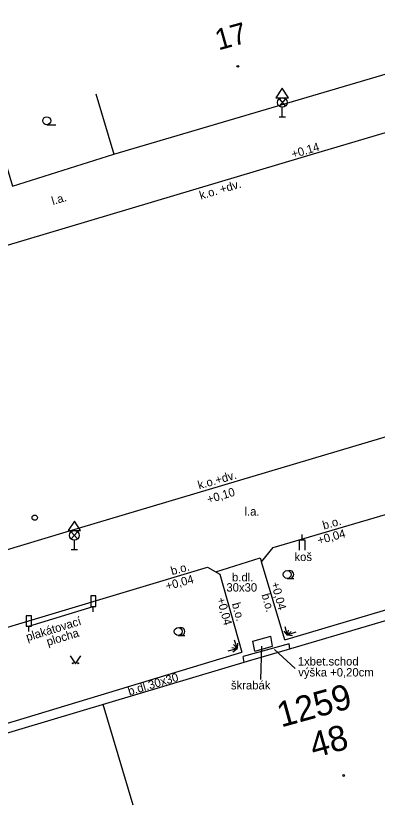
# Model space of a CAD drawing. Extents: x -597333 to -596488, y -1158921 to -1158644.
# Drawn here: x -596773.1 to -596755.95, y -1158752.5 to -1158714.98 of the extents above; entities that cross this region are included whole.
import ezdxf

# ---------------------------------------------------------------- set-up
doc = ezdxf.new("R2010")
doc.units = 0
for name, color, linetype in [('Vrstva 10', 7, 'Continuous'), ('Vrstva 14', 7, 'Continuous'), ('Vrstva 15', 7, 'Continuous'), ('Vrstva 24', 7, 'Continuous'), ('Vrstva 4', 7, 'Continuous'), ('Vrstva 43', 7, 'Continuous'), ('Vrstva 44', 7, 'Continuous'), ('Vrstva 49', 7, 'Continuous'), ('Vrstva 5', 7, 'Continuous'), ('Vrstva 50', 7, 'Continuous'), ('Vrstva 7', 7, 'Continuous')]:
    doc.layers.add(name, color=color, linetype=linetype)

msp = doc.modelspace()

# ---------------------------------------------------------------- linework, layer by layer
at = {"layer": 'Vrstva 10'}
msp.add_lwpolyline([(-596775.29, -1158716.24), (-596773.25, -1158723.07), (-596768.45, -1158721.56)], dxfattribs=at)
at = {"layer": 'Vrstva 14'}
for p, q in [((-596771.63, -1158720.156), (-596771.192, -1158720.156)), ((-596760.22, -1158741.718), (-596759.907, -1158741.718)), ((-596765.39, -1158744.428), (-596765.078, -1158744.428))]:
    msp.add_line(p, q, dxfattribs=at)
msp.add_lwpolyline([(-596770.515, -1158745.398), (-596770.265, -1158745.773), (-596770.015, -1158745.398)], dxfattribs=at)
for centre, radius in [((-596771.63, -1158719.968), 0.188), ((-596760.22, -1158741.53), 0.188), ((-596765.39, -1158744.24), 0.188), ((-596770.39, -1158745.748), 0.025), ((-596770.14, -1158745.748), 0.025)]:
    msp.add_circle(centre, radius, dxfattribs=at)
for centre in [(-596760.095, -1158741.53), (-596765.265, -1158744.24)]:
    msp.add_arc(centre, 0.188, 249.4944, 109.0474, dxfattribs=at)
at = {"layer": 'Vrstva 15'}
for p, q in [((-596759.51, -1158739.88), (-596759.51, -1158739.63)), ((-596772.48, -1158743.99), (-596769.42, -1158743.05)), ((-596769.42, -1158743.3), (-596769.42, -1158743.05)), ((-596772.48, -1158744.24), (-596772.48, -1158743.99))]:
    msp.add_line(p, q, dxfattribs=at)
msp.add_lwpolyline([(-596759.635, -1158740.38), (-596759.635, -1158739.88), (-596759.385, -1158739.88), (-596759.385, -1158740.38)], dxfattribs=at)
for points in [[(-596769.545, -1158743.05), (-596769.295, -1158743.05), (-596769.295, -1158742.55), (-596769.545, -1158742.55)], [(-596772.605, -1158743.99), (-596772.355, -1158743.99), (-596772.355, -1158743.49), (-596772.605, -1158743.49)]]:
    msp.add_lwpolyline(points, close=True, dxfattribs=at)
for centre in [(-596762.562, -1158717.382), (-596757.537, -1158751.081)]:
    msp.add_circle(centre, 0.0438, dxfattribs=at)
at = {"layer": 'Vrstva 24'}
msp.add_circle((-596772.2, -1158738.83), 0.125, dxfattribs=at)
at = {"layer": 'Vrstva 4'}
for p, q in [((-596769.301, -1158718.683), (-596768.45, -1158721.56)), ((-596760.468, -1158745.173), (-596744.352, -1158740.392)), ((-596767.525, -1158752.495), (-596768.956, -1158747.704))]:
    msp.add_line(p, q, dxfattribs=at)
for points in [[(-596768.45, -1158721.56), (-596752.997, -1158716.989)], [(-596760.09, -1158745.061), (-596760.13, -1158744.82), (-596762.31, -1158745.43)], [(-596762.264, -1158745.707), (-596762.31, -1158745.43)], [(-596778.32, -1158750.5), (-596761.94, -1158745.61)]]:
    msp.add_lwpolyline(points, dxfattribs=at)
at = {"layer": 'Vrstva 44'}
for p, q in [((-596760.3, -1158718.93), (-596760.6, -1158719.274)), ((-596760.6, -1158718.93), (-596760.3, -1158719.274)), ((-596760.45, -1158719.78), (-596760.45, -1158719.33)), ((-596760.6, -1158719.78), (-596760.3, -1158719.78)), ((-596770.17, -1158739.5), (-596770.47, -1158739.844)), ((-596770.47, -1158739.5), (-596770.17, -1158739.844)), ((-596770.32, -1158740.35), (-596770.32, -1158739.9)), ((-596770.47, -1158740.35), (-596770.17, -1158740.35))]:
    msp.add_line(p, q, dxfattribs=at)
for points in [[(-596760.75, -1158718.874), (-596760.15, -1158718.874), (-596760.45, -1158718.424), (-596760.75, -1158718.874)], [(-596770.62, -1158739.444), (-596770.02, -1158739.444), (-596770.32, -1158738.994), (-596770.62, -1158739.444)]]:
    msp.add_lwpolyline(points, dxfattribs=at)
for centre in [(-596760.45, -1158719.102), (-596770.32, -1158739.672)]:
    msp.add_circle(centre, 0.228, dxfattribs=at)
at = {"layer": 'Vrstva 49'}
for p, q in [((-596760.373, -1158744.226), (-596760.215, -1158744.419)), ((-596760.169, -1158744.174), (-596760.215, -1158744.419)), ((-596760.036, -1158744.245), (-596760.215, -1158744.419)), ((-596759.966, -1158744.445), (-596760.215, -1158744.419)), ((-596762.844, -1158744.999), (-596762.599, -1158745.045)), ((-596762.792, -1158745.203), (-596762.599, -1158745.045)), ((-596762.773, -1158744.865), (-596762.599, -1158745.045)), ((-596762.573, -1158744.796), (-596762.599, -1158745.045))]:
    msp.add_line(p, q, dxfattribs=at)
for points in [[(-596760.322, -1158743.999), (-596760.215, -1158744.419)], [(-596759.805, -1158744.277), (-596760.215, -1158744.419)], [(-596762.741, -1158744.635), (-596762.599, -1158745.045)], [(-596763.019, -1158745.152), (-596762.599, -1158745.045)], [(-596761.438, -1158744.943), (-596761.488, -1158746.527)], [(-596760.816, -1158745.102), (-596759.838, -1158745.993)]]:
    msp.add_lwpolyline(points, dxfattribs=at)
at = {"layer": 'Vrstva 5'}
msp.add_line((-596761.94, -1158745.61), (-596760.469, -1158745.171), dxfattribs=at)
at = {"layer": 'Vrstva 7'}
msp.add_line((-596760.33, -1158744.63), (-596744.76, -1158740.02), dxfattribs=at)
for points in [[(-596838.86, -1158745.39), (-596830.57, -1158742.87), (-596825.17, -1158741.29), (-596822.55, -1158740.48), (-596812.47, -1158737.51), (-596803.27, -1158734.78), (-596791.33, -1158731.21), (-596774.68, -1158726.23), (-596759.56, -1158721.71), (-596748.14, -1158718.32), (-596736.94, -1158714.98)], [(-596782.84, -1158743.16), (-596770.71, -1158739.5), (-596748.23, -1158732.81), (-596734.11, -1158728.61), (-596733.99, -1158728.79), (-596728.47, -1158727.15), (-596728.46, -1158726.93), (-596719.98, -1158724.4)], [(-596760.89, -1158740.25), (-596746.61, -1158736.05), (-596745.96, -1158736.23), (-596745.66, -1158737.13), (-596744.76, -1158740.02)], [(-596760.33, -1158744.63), (-596761.43, -1158740.93), (-596760.89, -1158740.25)], [(-596763.6, -1158741.41), (-596761.5, -1158740.74), (-596761.43, -1158740.93)], [(-596778.92, -1158745.66), (-596764, -1158741.19), (-596763.41, -1158741.51), (-596762.37, -1158745.23)], [(-596761.85, -1158744.7), (-596761, -1158744.46)], [(-596761.76, -1158745.17), (-596761.85, -1158744.7)], [(-596761.76, -1158745.17), (-596760.91, -1158744.93), (-596761, -1158744.46)], [(-596773.07, -1158748.47), (-596762.37, -1158745.23)], [(-596778.92, -1158745.66), (-596779.34, -1158746.2), (-596778.16, -1158749.96), (-596773.07, -1158748.47)]]:
    msp.add_lwpolyline(points, dxfattribs=at)

# ---------------------------------------------------------------- texts
at = {"layer": 'Vrstva 43'}
for s, height, p in [('17', 1, (-596763.479, -1158716.629)), ('1259', 1.2, (-596760.505, -1158748.806)), ('48', 1.2, (-596758.951, -1158750.261))]:
    msp.add_text(s, height=height, rotation=15.5254, dxfattribs=at).set_placement(p)
at = {"layer": 'Vrstva 49'}
for s, rotation, p in [('k.o. +dv.', 16.569, (-596764.317, -1158723.717)), ('l.a.', 16.5505, (-596771.335, -1158723.977)), ('k.o.+dv.', 16.0773, (-596764.397, -1158737.488)), ('b.o.', 15.3727, (-596758.479, -1158739.395)), ('b.o.', 15.3727, (-596765.682, -1158741.567)), ('b.o.', 285.3727, (-596761.437, -1158742.491)), ('b.o.', 285.3727, (-596762.849, -1158742.922)), ('plakátovací', 17.0764, (-596772.544, -1158744.708)), ('plocha', 17.0764, (-596771.572, -1158744.932)), ('b.dl.30x30', 16.6222, (-596767.71, -1158747.283))]:
    msp.add_text(s, height=0.4, rotation=rotation, dxfattribs=at).set_placement(p)
for s, p in [('l.a.', (-596762.245, -1158738.732)), ('koš', (-596759.873, -1158740.892)), ('b.dl.', (-596762.836, -1158741.858)), ('30x30', (-596763.103, -1158742.344)), ('1xbet.schod', (-596759.713, -1158745.857)), ('škrabák', (-596762.888, -1158746.993))]:
    msp.add_text(s, height=0.4, dxfattribs=at).set_placement(p)
at = {"layer": 'Vrstva 50'}
for s, rotation, p in [('+0.14', 16.5375, (-596759.952, -1158721.758)), ('+0,10', 16.8584, (-596763.956, -1158738.167)), ('+0,04', 15.3727, (-596758.722, -1158740.11)), ('+0,04', 15.3727, (-596765.925, -1158742.282)), ('+0,04', 285.3727, (-596760.99, -1158741.944)), ('+0,04', 285.3727, (-596763.564, -1158742.678))]:
    msp.add_text(s, height=0.4, rotation=rotation, dxfattribs=at).set_placement(p)
msp.add_text('výška +0,20cm', height=0.4, dxfattribs=at).set_placement((-596759.695, -1158746.378))

doc.saveas('drawing.dxf')
